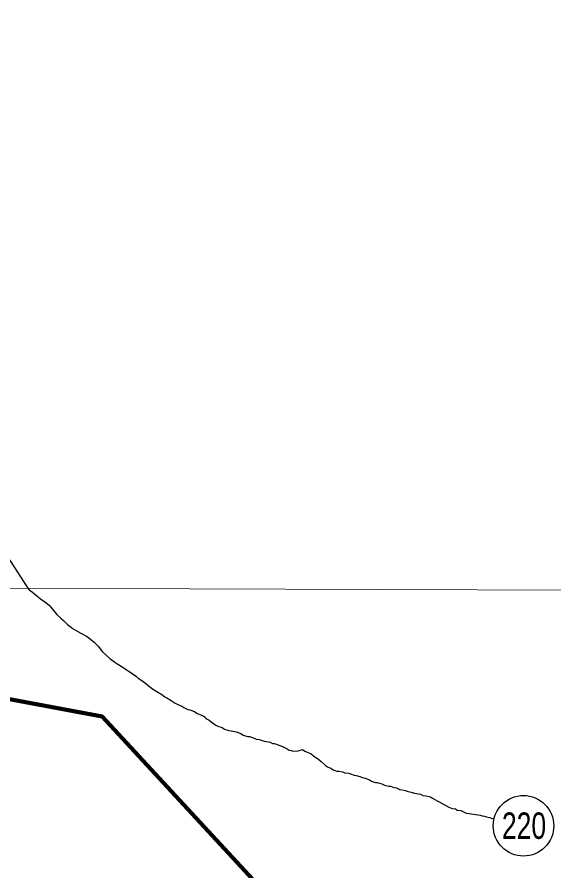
# Model space of a CAD drawing. Extents: x -1643653 to 4543381, y 1624270 to 13878484.
# Drawn here: x 652366 to 659476, y 8945806 to 8957118 of the extents above; entities that cross this region are included whole.
import ezdxf
from ezdxf.enums import TextEntityAlignment as Align

# ---------------------------------------------------------------- set-up
doc = ezdxf.new("R2010")
doc.units = 0
doc.header["$LTSCALE"] = 200
for name, color, linetype, lineweight in [('1', 7, 'Continuous', 13), ('12', 7, 'Continuous', 25), ('48', 7, 'Continuous', 25), ('57', 7, 'Continuous', 13), ('59', 7, 'Continuous', 53), ('60', 7, 'Continuous', 13), ('9', 7, 'Continuous', 90)]:
    doc.layers.add(name, color=color, linetype=linetype, lineweight=lineweight)

msp = doc.modelspace()

# ---------------------------------------------------------------- linework, layer by layer
at = {"layer": '1'}
msp.add_line((565315.3, 8949866.8), (791497.7, 8949052.2), dxfattribs=at)
at = {"layer": '12'}
for points in [[(652015.9, 8950156.6), (652017.2, 8950142.2), (652048.2, 8950106.5), (652073.3, 8950084.6), (652100.6, 8950064.8), (652145.1, 8950025.5), (652162.5, 8950012.1), (652213.7, 8949988.4), (652275.7, 8949914.2), (652507.9, 8949552.8)], [(652507.9, 8949552.8), (652526.9, 8949530.3), (652569.2, 8949497.5), (652626.3, 8949452.1), (652693.5, 8949399.1), (652728.3, 8949373.8), (652790.5, 8949328.3), (652815.3, 8949300.6), (652867.3, 8949232.7), (652894.6, 8949204.9), (652949.2, 8949149.5), (652979, 8949124.3), (653033.6, 8949071.3), (653085.8, 8949030.9), (653110.7, 8949013.2), (653173, 8948977.8), (653212.8, 8948957.5), (653287.6, 8948916.9), (653314.9, 8948894.2), (653367.1, 8948853.8), (653392, 8948833.6), (653441.6, 8948785.7)], [(653441.6, 8948785.7), (653498.6, 8948710.3), (653535.8, 8948672.5), (653595.5, 8948622), (653660.1, 8948571.5), (653702.4, 8948546.2), (653779.6, 8948498.1), (653804.4, 8948477.9), (653859.2, 8948442.5), (653889.1, 8948422.3), (653946.3, 8948381.8), (653971.1, 8948361.6), (654018.4, 8948328.8), (654070.6, 8948288.4), (654100.4, 8948263.2), (654160.1, 8948220.2), (654195, 8948194.9), (654262.2, 8948156.9), (654284.6, 8948141.8), (654324.4, 8948114), (654351.8, 8948098.8), (654409.1, 8948063.3), (654458.8, 8948030.5), (654488.7, 8948015.2), (654548.5, 8947987.3), (654573.4, 8947972.1), (654628.3, 8947946.7), (654655.7, 8947941.5), (654718.1, 8947918.6), (654752.9, 8947893.3), (654800.3, 8947875.5), (654842.6, 8947850.2), (654867.5, 8947825), (654909.8, 8947804.7), (654937.1, 8947779.4), (654999.3, 8947739), (655026.8, 8947723.8), (655084.1, 8947705.9), (655111.5, 8947685.7), (655168.9, 8947665.2), (655203.9, 8947662.5), (655268.8, 8947647.1), (655328.6, 8947626.6), (655358.5, 8947606.4), (655415.9, 8947588.5), (655445.9, 8947588.3), (655505.8, 8947565.4), (655533.2, 8947550.2), (655578.2, 8947547.4), (655600.6, 8947539.7), (655640.5, 8947524.4), (655668, 8947521.8), (655698, 8947514), (655720.4, 8947511.4), (655747.8, 8947496.2), (655772.8, 8947493.5), (655802.8, 8947483.3), (655835.2, 8947473.1), (655860.1, 8947462.9), (655892.6, 8947450.2), (655915, 8947435), (655942.4, 8947424.8), (655969.7, 8947404.6), (655997.2, 8947401.9), (656019.7, 8947391.7), (656089.8, 8947398.8)], [(656089.8, 8947398.8), (656144.9, 8947413.4), (656177.2, 8947393.2), (656259.5, 8947355.1), (656294.3, 8947332.3), (656364, 8947281.8), (656393.8, 8947254.1), (656450.9, 8947201.1), (656475.8, 8947185.9), (656523.2, 8947168.1), (656553, 8947145.4), (656602.9, 8947127.5), (656627.9, 8947127.3), (656675.4, 8947119.5), (656705.3, 8947104.3), (656757.8, 8947101.5), (656780.2, 8947093.8), (656830.1, 8947073.4), (656857.6, 8947070.8), (656907.5, 8947055.4), (656952.4, 8947040.1), (656977.4, 8947034.9), (657032.2, 8947012), (657059.6, 8946996.8), (657112, 8946978.9), (657137, 8946978.8), (657199.4, 8946960.8), (657234.3, 8946943.1), (657289.2, 8946927.7), (657311.7, 8946927.6), (657356.6, 8946912.2), (657391.6, 8946904.5), (657431.4, 8946884.2), (657466.4, 8946879), (657506.4, 8946871.2), (657546.3, 8946858.4), (657586.2, 8946850.6), (657631.1, 8946835.3), (657656.1, 8946832.6), (657708.6, 8946824.8), (657741, 8946807.1), (657781, 8946801.8), (657808.4, 8946794.1), (657840.9, 8946788.9), (657868.2, 8946768.7), (657898.1, 8946753.4), (657930.5, 8946735.7), (657965.4, 8946717.9), (658005.2, 8946692.6), (658045.1, 8946672.3), (658085, 8946652.1), (658129.8, 8946634.2), (658172.3, 8946628.9), (658194.7, 8946611.3), (658242.2, 8946608.4), (658277.1, 8946590.7), (658314.5, 8946572.9), (658354.4, 8946567.7), (658406.9, 8946559.8), (658439.3, 8946552.1), (658501.8, 8946544.2), (658524.3, 8946536.5), (658556.7, 8946531.3), (658581.7, 8946523.6), (658624.1, 8946515.8), (658678.1, 8946495.9)]]:
    msp.add_lwpolyline(points, dxfattribs=at)
at = {"layer": '48'}
msp.add_circle((659073.8, 8946403.8), 401.3, dxfattribs=at)
at = {"layer": '57'}
for points in [[(645793.1, 8949290.9), (653495.4, 8947850), (659002.1, 8941889), (661559, 8940382.7)], [(661559, 8940382.7), (659002.1, 8941889), (653495.4, 8947850), (645793.1, 8949290.9)]]:
    msp.add_lwpolyline(points, dxfattribs=at)
at = {"layer": '59'}
msp.add_lwpolyline([(645793.1, 8949290.9), (653495.4, 8947850), (659002.1, 8941889), (661559, 8940382.7), (661583.1, 8940454)], dxfattribs=at)
at = {"layer": '60', "lineweight": 25}
msp.add_spline([(814781, 9009175.5), (814787.2, 9009173.4), (814796.9, 9009173.4), (814799.4, 9009172.4), (814805.1, 9009174.5), (814805.6, 9009176.5), (814811.7, 9009179.5), (814811.7, 9009179.5), (814801.5, 9009181), (814790.7, 9009181.5), (814784.1, 9009183.1), (814777.4, 9009185.1), (814778.4, 9009175.5)], degree=3, dxfattribs=at)
at = {"layer": '9'}
msp.add_lwpolyline([(645793.1, 8949290.9), (653495.4, 8947850), (659002.1, 8941889), (662654, 8939737.7), (668185.2, 8933928.8)], dxfattribs=at)
msp.add_spline([(637260.6, 8972975.8), (641524.5, 8971056.2), (652526.1, 8965412.7), (653164.3, 8965062.8), (670790.5, 8953770.1), (686194, 8943929.9), (696283.3, 8937647.1)], degree=3, dxfattribs=at)

# ---------------------------------------------------------------- texts
at = {"layer": '48', "width": 0.75}
msp.add_text('220', height=350, dxfattribs=at).set_placement((659080.5, 8946230.4), align=Align.CENTER)

doc.saveas('drawing.dxf')
